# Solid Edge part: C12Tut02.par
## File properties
Author: ASHUTOSH
Template: iso metric part.par
Last saved by: Rajat Kamboj
Revision: 3
Application: Solid Edge
Accuracy: 0.990
Username: ASHUTOSH
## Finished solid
Body 1: solid body, 20 faces, 54 edges, 36 vertices.
  Faces by surface: plane 13, cylinder 7
  Edges by curve: line 40, circle 14
Bounding box of the edges (mm): 175.000 x 50.000 x 89.138, from (-48, -25, 0) to (127, 25, 89.1384).
Cylindrical faces by radius (mm): R5 x2, R6 x1, R9.7733 x1, R15 x2, R27 x1
Planar faces by outward normal: +y 3, +z 1, -y 3, -z 1, oblique 5
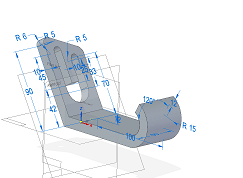
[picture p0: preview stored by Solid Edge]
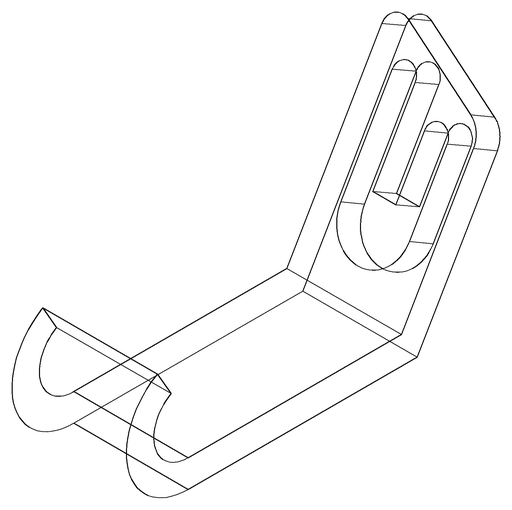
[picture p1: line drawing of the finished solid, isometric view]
